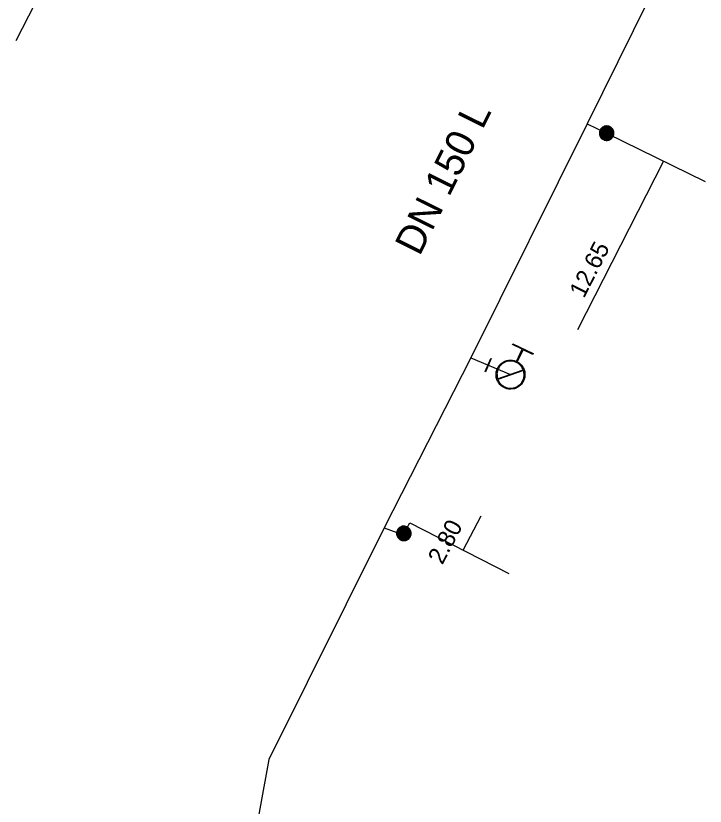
# Model space of a CAD drawing. Extents: x -820257 to -819974, y -1070894 to -1070484.
# Drawn here: x -820136.2 to -820088.3, y -1070800.1 to -1070745.2 of the extents above; entities that cross this region are included whole.
import ezdxf

# ---------------------------------------------------------------- set-up
doc = ezdxf.new("R2010")
doc.units = 0
for name, color, linetype in [('Hyd-odbočka', 7, 'Continuous'), ('Hyd-šoupě', 7, 'Continuous'), ('Hydrant', 7, 'Continuous'), ('Oměrka vodovodu', 7, 'Continuous'), ('Oměrka-text', 7, 'Continuous'), ('Přípojka vodovodu', 7, 'Continuous'), ('Přípojkový uzávěr', 7, 'Continuous'), ('Roz-řad', 7, 'Continuous'), ('Roz-řad-popis základní', 7, 'Continuous')]:
    doc.layers.add(name, color=color, linetype=linetype)

msp = doc.modelspace()

# ---------------------------------------------------------------- linework, layer by layer
at = {"layer": 'Hyd-odbočka'}
msp.add_line((-820104.571, -1070768.915), (-820101.807, -1070770.091), dxfattribs=at)
at = {"layer": 'Hyd-šoupě'}
msp.add_lwpolyline([(-820103.156, -1070768.973), (-820103.548, -1070769.894), (-820103.576, -1070769.881), (-820103.185, -1070768.961), (-820103.156, -1070768.973)], dxfattribs=at)
at = {"layer": 'Hydrant'}
for points in [[(-820101.402, -1070769.176), (-820100.997, -1070768.331), (-820101.673, -1070768.006), (-820101.646, -1070767.95), (-820100.237, -1070768.626), (-820100.264, -1070768.683), (-820100.94, -1070768.358), (-820101.346, -1070769.203)], [(-820102.703, -1070770.374), (-820100.931, -1070769.751)], [(-820100.911, -1070769.809), (-820102.684, -1070770.433)]]:
    msp.add_lwpolyline(points, dxfattribs=at)
for points in [[(-820101.346, -1070769.203), (-820101.136, -1070769.312), (-820100.986, -1070769.519), (-820100.827, -1070769.738), (-820100.81, -1070770.013), (-820100.792, -1070770.288), (-820100.905, -1070770.524), (-820101.018, -1070770.758), (-820101.24, -1070770.916), (-820101.462, -1070771.074), (-820101.734, -1070771.089), (-820102.005, -1070771.105), (-820102.24, -1070770.993), (-820102.474, -1070770.88), (-820102.632, -1070770.658), (-820102.789, -1070770.436), (-820102.805, -1070770.164), (-820102.821, -1070769.893), (-820102.708, -1070769.658), (-820102.595, -1070769.422), (-820102.37, -1070769.264), (-820102.144, -1070769.106), (-820101.874, -1070769.093), (-820101.62, -1070769.08), (-820101.402, -1070769.176)], [(-820100.931, -1070769.751), (-820100.972, -1070769.647), (-820101.038, -1070769.555), (-820101.188, -1070769.348), (-820101.401, -1070769.246), (-820101.614, -1070769.144), (-820101.869, -1070769.156), (-820102.124, -1070769.168), (-820102.335, -1070769.316), (-820102.546, -1070769.464), (-820102.652, -1070769.685), (-820102.758, -1070769.905), (-820102.741, -1070770.16), (-820102.736, -1070770.271), (-820102.703, -1070770.374)], [(-820102.684, -1070770.433), (-820102.645, -1070770.532), (-820102.579, -1070770.622), (-820102.433, -1070770.831), (-820102.213, -1070770.936), (-820101.993, -1070771.042), (-820101.737, -1070771.027), (-820101.482, -1070771.012), (-820101.275, -1070770.864), (-820101.067, -1070770.717), (-820100.962, -1070770.497), (-820100.855, -1070770.275), (-820100.872, -1070770.018), (-820100.88, -1070769.908), (-820100.911, -1070769.809)]]:
    msp.add_open_spline(points, degree=3, dxfattribs=at)
at = {"layer": 'Oměrka vodovodu'}
for p, q in [((-820091.178, -1070755.26), (-820097.156, -1070766.982)), ((-820105.102, -1070782.288), (-820103.856, -1070779.911))]:
    msp.add_line(p, q, dxfattribs=at)
at = {"layer": 'Přípojka vodovodu'}
for points in [[(-820124.049, -1070723.282), (-820124.733, -1070724.617), (-820136.162, -1070746.911)], [(-820096.482, -1070752.661), (-820095.135, -1070753.321), (-820088.29, -1070756.675)], [(-820110.577, -1070780.742), (-820109.272, -1070781.216), (-820109.216, -1070781.119), (-820108.794, -1070780.397), (-820101.932, -1070783.911)]]:
    msp.add_lwpolyline(points, dxfattribs=at)
at = {"layer": 'Přípojkový uzávěr'}
for points in [[(-820094.915, -1070752.872), (-820094.802, -1070752.927), (-820094.723, -1070753.038), (-820094.644, -1070753.148), (-820094.636, -1070753.286), (-820094.629, -1070753.424), (-820094.686, -1070753.541), (-820094.743, -1070753.658), (-820094.855, -1070753.736), (-820094.966, -1070753.814), (-820095.102, -1070753.82), (-820095.238, -1070753.827), (-820095.355, -1070753.77), (-820095.472, -1070753.713), (-820095.55, -1070753.601), (-820095.628, -1070753.49), (-820095.634, -1070753.354), (-820095.641, -1070753.218), (-820095.584, -1070753.101), (-820095.527, -1070752.984), (-820095.413, -1070752.905), (-820095.3, -1070752.827), (-820095.165, -1070752.821), (-820095.029, -1070752.816), (-820094.915, -1070752.872)], [(-820094.936, -1070752.914), (-820095.039, -1070752.864), (-820095.162, -1070752.868), (-820095.285, -1070752.873), (-820095.387, -1070752.944), (-820095.49, -1070753.016), (-820095.542, -1070753.122), (-820095.594, -1070753.228), (-820095.588, -1070753.351), (-820095.582, -1070753.474), (-820095.511, -1070753.575), (-820095.44, -1070753.676), (-820095.335, -1070753.728), (-820095.229, -1070753.78), (-820095.105, -1070753.774), (-820094.982, -1070753.767), (-820094.881, -1070753.697), (-820094.78, -1070753.626), (-820094.728, -1070753.521), (-820094.676, -1070753.414), (-820094.683, -1070753.289), (-820094.691, -1070753.164), (-820094.762, -1070753.064), (-820094.833, -1070752.964), (-820094.936, -1070752.914)], [(-820094.951, -1070752.945), (-820094.856, -1070752.991), (-820094.79, -1070753.084), (-820094.724, -1070753.176), (-820094.717, -1070753.292), (-820094.711, -1070753.407), (-820094.759, -1070753.506), (-820094.807, -1070753.604), (-820094.9, -1070753.669), (-820094.993, -1070753.734), (-820095.107, -1070753.74), (-820095.222, -1070753.745), (-820095.32, -1070753.697), (-820095.417, -1070753.649), (-820095.483, -1070753.556), (-820095.548, -1070753.462), (-820095.554, -1070753.349), (-820095.559, -1070753.235), (-820095.511, -1070753.137), (-820095.463, -1070753.038), (-820095.368, -1070752.973), (-820095.274, -1070752.907), (-820095.16, -1070752.902), (-820095.046, -1070752.898), (-820094.951, -1070752.945)], [(-820094.971, -1070752.984), (-820095.111, -1070752.915), (-820095.257, -1070752.966), (-820095.403, -1070753.017), (-820095.472, -1070753.156), (-820095.54, -1070753.296), (-820095.49, -1070753.443), (-820095.439, -1070753.589), (-820095.301, -1070753.657), (-820095.161, -1070753.726), (-820095.014, -1070753.676), (-820094.867, -1070753.626), (-820094.798, -1070753.486), (-820094.73, -1070753.347), (-820094.78, -1070753.2), (-820094.829, -1070753.053), (-820094.971, -1070752.984)], [(-820094.991, -1070753.025), (-820094.868, -1070753.085), (-820094.824, -1070753.214), (-820094.781, -1070753.342), (-820094.841, -1070753.464), (-820094.901, -1070753.586), (-820095.029, -1070753.63), (-820095.157, -1070753.674), (-820095.28, -1070753.614), (-820095.403, -1070753.554), (-820095.446, -1070753.426), (-820095.49, -1070753.298), (-820095.43, -1070753.175), (-820095.37, -1070753.053), (-820095.242, -1070753.009), (-820095.114, -1070752.965), (-820094.991, -1070753.025)], [(-820095.008, -1070753.061), (-820095.116, -1070753.008), (-820095.229, -1070753.047), (-820095.342, -1070753.085), (-820095.395, -1070753.193), (-820095.447, -1070753.3), (-820095.409, -1070753.413), (-820095.37, -1070753.526), (-820095.262, -1070753.579), (-820095.155, -1070753.631), (-820095.042, -1070753.593), (-820094.929, -1070753.554), (-820094.876, -1070753.447), (-820094.824, -1070753.339), (-820094.862, -1070753.226), (-820094.9, -1070753.114), (-820095.008, -1070753.061)], [(-820095.025, -1070753.096), (-820094.931, -1070753.142), (-820094.898, -1070753.24), (-820094.865, -1070753.338), (-820094.911, -1070753.431), (-820094.956, -1070753.524), (-820095.054, -1070753.558), (-820095.152, -1070753.591), (-820095.245, -1070753.545), (-820095.338, -1070753.5), (-820095.372, -1070753.402), (-820095.405, -1070753.304), (-820095.36, -1070753.211), (-820095.314, -1070753.118), (-820095.217, -1070753.084), (-820095.119, -1070753.05), (-820095.025, -1070753.096)], [(-820095.046, -1070753.138), (-820095.122, -1070753.101), (-820095.201, -1070753.128), (-820095.28, -1070753.155), (-820095.318, -1070753.231), (-820095.355, -1070753.307), (-820095.328, -1070753.386), (-820095.3, -1070753.466), (-820095.225, -1070753.503), (-820095.149, -1070753.54), (-820095.07, -1070753.513), (-820094.99, -1070753.486), (-820094.953, -1070753.41), (-820094.916, -1070753.334), (-820094.943, -1070753.254), (-820094.97, -1070753.175), (-820095.046, -1070753.138)], [(-820095.061, -1070753.169), (-820094.998, -1070753.2), (-820094.975, -1070753.266), (-820094.953, -1070753.331), (-820094.984, -1070753.394), (-820095.015, -1070753.458), (-820095.081, -1070753.48), (-820095.147, -1070753.502), (-820095.209, -1070753.472), (-820095.272, -1070753.441), (-820095.295, -1070753.375), (-820095.317, -1070753.309), (-820095.286, -1070753.246), (-820095.256, -1070753.183), (-820095.19, -1070753.161), (-820095.124, -1070753.138), (-820095.061, -1070753.169)], [(-820095.08, -1070753.209), (-820095.127, -1070753.186), (-820095.176, -1070753.203), (-820095.224, -1070753.22), (-820095.247, -1070753.266), (-820095.27, -1070753.312), (-820095.253, -1070753.361), (-820095.236, -1070753.41), (-820095.19, -1070753.433), (-820095.144, -1070753.456), (-820095.095, -1070753.439), (-820095.046, -1070753.422), (-820095.023, -1070753.376), (-820095, -1070753.33), (-820095.017, -1070753.281), (-820095.033, -1070753.232), (-820095.08, -1070753.209)], [(-820095.101, -1070753.251), (-820095.071, -1070753.265), (-820095.061, -1070753.295), (-820095.051, -1070753.325), (-820095.065, -1070753.355), (-820095.079, -1070753.384), (-820095.11, -1070753.395), (-820095.14, -1070753.406), (-820095.17, -1070753.391), (-820095.199, -1070753.377), (-820095.209, -1070753.346), (-820095.22, -1070753.315), (-820095.206, -1070753.286), (-820095.191, -1070753.257), (-820095.16, -1070753.247), (-820095.13, -1070753.236), (-820095.101, -1070753.251)], [(-820095.115, -1070753.279), (-820095.132, -1070753.27), (-820095.151, -1070753.276), (-820095.169, -1070753.282), (-820095.178, -1070753.3), (-820095.186, -1070753.318), (-820095.18, -1070753.336), (-820095.174, -1070753.354), (-820095.156, -1070753.363), (-820095.138, -1070753.372), (-820095.12, -1070753.365), (-820095.102, -1070753.359), (-820095.093, -1070753.341), (-820095.085, -1070753.323), (-820095.091, -1070753.305), (-820095.097, -1070753.288), (-820095.115, -1070753.279)], [(-820109.648, -1070780.868), (-820109.584, -1070780.759), (-820109.468, -1070780.688), (-820109.352, -1070780.617), (-820109.214, -1070780.619), (-820109.076, -1070780.622), (-820108.963, -1070780.688), (-820108.851, -1070780.753), (-820108.782, -1070780.87), (-820108.712, -1070780.987), (-820108.715, -1070781.123), (-820108.718, -1070781.259), (-820108.784, -1070781.372), (-820108.849, -1070781.483), (-820108.966, -1070781.553), (-820109.083, -1070781.623), (-820109.219, -1070781.62), (-820109.355, -1070781.617), (-820109.467, -1070781.551), (-820109.58, -1070781.485), (-820109.651, -1070781.367), (-820109.721, -1070781.248), (-820109.716, -1070781.112), (-820109.712, -1070780.977), (-820109.648, -1070780.868)], [(-820109.607, -1070780.891), (-820109.665, -1070780.99), (-820109.669, -1070781.113), (-820109.673, -1070781.236), (-820109.61, -1070781.343), (-820109.546, -1070781.451), (-820109.444, -1070781.511), (-820109.342, -1070781.57), (-820109.219, -1070781.573), (-820109.096, -1070781.576), (-820108.99, -1070781.512), (-820108.884, -1070781.449), (-820108.825, -1070781.348), (-820108.765, -1070781.246), (-820108.762, -1070781.122), (-820108.759, -1070780.999), (-820108.822, -1070780.893), (-820108.885, -1070780.787), (-820108.987, -1070780.728), (-820109.089, -1070780.668), (-820109.215, -1070780.666), (-820109.34, -1070780.664), (-820109.445, -1070780.728), (-820109.55, -1070780.792), (-820109.607, -1070780.891)], [(-820109.578, -1070780.908), (-820109.524, -1070780.817), (-820109.428, -1070780.758), (-820109.331, -1070780.699), (-820109.215, -1070780.7), (-820109.099, -1070780.702), (-820109.004, -1070780.758), (-820108.91, -1070780.812), (-820108.852, -1070780.91), (-820108.793, -1070781.008), (-820108.796, -1070781.122), (-820108.799, -1070781.236), (-820108.854, -1070781.331), (-820108.909, -1070781.424), (-820109.007, -1070781.483), (-820109.105, -1070781.542), (-820109.219, -1070781.539), (-820109.333, -1070781.536), (-820109.427, -1070781.481), (-820109.521, -1070781.426), (-820109.58, -1070781.327), (-820109.639, -1070781.227), (-820109.635, -1070781.113), (-820109.631, -1070780.999), (-820109.578, -1070780.908)], [(-820109.54, -1070780.931), (-820109.619, -1070781.066), (-820109.579, -1070781.215), (-820109.539, -1070781.365), (-820109.404, -1070781.443), (-820109.27, -1070781.522), (-820109.12, -1070781.482), (-820108.97, -1070781.442), (-820108.892, -1070781.309), (-820108.814, -1070781.174), (-820108.853, -1070781.024), (-820108.892, -1070780.874), (-820109.026, -1070780.796), (-820109.161, -1070780.717), (-820109.311, -1070780.756), (-820109.461, -1070780.795), (-820109.54, -1070780.931)], [(-820109.501, -1070780.954), (-820109.431, -1070780.836), (-820109.3, -1070780.802), (-820109.169, -1070780.767), (-820109.052, -1070780.836), (-820108.934, -1070780.905), (-820108.9, -1070781.036), (-820108.865, -1070781.167), (-820108.934, -1070781.285), (-820109.003, -1070781.403), (-820109.134, -1070781.437), (-820109.265, -1070781.472), (-820109.383, -1070781.403), (-820109.5, -1070781.334), (-820109.535, -1070781.203), (-820109.569, -1070781.072), (-820109.501, -1070780.954)], [(-820109.466, -1070780.974), (-820109.527, -1070781.078), (-820109.496, -1070781.193), (-820109.466, -1070781.308), (-820109.363, -1070781.369), (-820109.259, -1070781.429), (-820109.144, -1070781.399), (-820109.028, -1070781.369), (-820108.968, -1070781.265), (-820108.908, -1070781.162), (-820108.938, -1070781.046), (-820108.968, -1070780.931), (-820109.072, -1070780.87), (-820109.175, -1070780.81), (-820109.29, -1070780.84), (-820109.406, -1070780.87), (-820109.466, -1070780.974)], [(-820109.432, -1070780.994), (-820109.379, -1070780.903), (-820109.279, -1070780.877), (-820109.179, -1070780.851), (-820109.089, -1070780.903), (-820109, -1070780.956), (-820108.974, -1070781.056), (-820108.948, -1070781.156), (-820109, -1070781.246), (-820109.052, -1070781.335), (-820109.152, -1070781.361), (-820109.252, -1070781.387), (-820109.341, -1070781.335), (-820109.431, -1070781.283), (-820109.458, -1070781.183), (-820109.485, -1070781.084), (-820109.432, -1070780.994)], [(-820109.392, -1070781.017), (-820109.434, -1070781.09), (-820109.413, -1070781.171), (-820109.392, -1070781.252), (-820109.319, -1070781.295), (-820109.246, -1070781.337), (-820109.165, -1070781.316), (-820109.084, -1070781.295), (-820109.041, -1070781.222), (-820108.999, -1070781.149), (-820109.02, -1070781.068), (-820109.041, -1070780.986), (-820109.114, -1070780.944), (-820109.187, -1070780.901), (-820109.268, -1070780.923), (-820109.349, -1070780.944), (-820109.392, -1070781.017)], [(-820109.362, -1070781.034), (-820109.327, -1070780.974), (-820109.259, -1070780.956), (-820109.192, -1070780.938), (-820109.132, -1070780.974), (-820109.071, -1070781.009), (-820109.053, -1070781.077), (-820109.036, -1070781.144), (-820109.071, -1070781.204), (-820109.106, -1070781.265), (-820109.174, -1070781.283), (-820109.241, -1070781.3), (-820109.301, -1070781.265), (-820109.362, -1070781.229), (-820109.38, -1070781.162), (-820109.397, -1070781.095), (-820109.362, -1070781.034)], [(-820109.324, -1070781.057), (-820109.35, -1070781.101), (-820109.337, -1070781.151), (-820109.324, -1070781.201), (-820109.279, -1070781.227), (-820109.234, -1070781.253), (-820109.184, -1070781.24), (-820109.134, -1070781.227), (-820109.108, -1070781.183), (-820109.082, -1070781.137), (-820109.095, -1070781.087), (-820109.108, -1070781.037), (-820109.153, -1070781.011), (-820109.197, -1070780.985), (-820109.247, -1070780.998), (-820109.297, -1070781.011), (-820109.324, -1070781.057)], [(-820109.284, -1070781.08), (-820109.267, -1070781.052), (-820109.236, -1070781.043), (-820109.205, -1070781.035), (-820109.177, -1070781.052), (-820109.149, -1070781.068), (-820109.14, -1070781.099), (-820109.132, -1070781.13), (-820109.149, -1070781.159), (-820109.165, -1070781.187), (-820109.196, -1070781.195), (-820109.228, -1070781.203), (-820109.255, -1070781.187), (-820109.284, -1070781.17), (-820109.292, -1070781.139), (-820109.3, -1070781.108), (-820109.284, -1070781.08)], [(-820109.257, -1070781.096), (-820109.266, -1070781.113), (-820109.262, -1070781.131), (-820109.257, -1070781.15), (-820109.24, -1070781.16), (-820109.223, -1070781.17), (-820109.204, -1070781.165), (-820109.185, -1070781.16), (-820109.176, -1070781.143), (-820109.165, -1070781.126), (-820109.171, -1070781.107), (-820109.176, -1070781.089), (-820109.192, -1070781.079), (-820109.21, -1070781.069), (-820109.228, -1070781.074), (-820109.246, -1070781.079), (-820109.257, -1070781.096)]]:
    msp.add_open_spline(points, degree=3, dxfattribs=at)
at = {"layer": 'Roz-řad'}
for points in [[(-820091.157, -1070741.885), (-820096.482, -1070752.661), (-820104.571, -1070768.915)], [(-820104.571, -1070768.915), (-820110.577, -1070780.742), (-820118.59, -1070796.818), (-820122.165, -1070816.376), (-820128.396, -1070848.754), (-820128.743, -1070850.133)]]:
    msp.add_lwpolyline(points, dxfattribs=at)

# ---------------------------------------------------------------- texts
at = {"layer": 'Oměrka-text'}
for s, rotation, p in [('12.65', 62.9793, (-820096.711, -1070764.837)), (' 2.80', 62.3369, (-820106.752, -1070783.746))]:
    msp.add_text(s, height=1.2, rotation=rotation, dxfattribs=at).set_placement(p)
at = {"layer": 'Roz-řad-popis základní'}
msp.add_text('DN 150 L', height=2, rotation=63.5422, dxfattribs=at).set_placement((-820108.127, -1070761.918))

doc.saveas('drawing.dxf')
